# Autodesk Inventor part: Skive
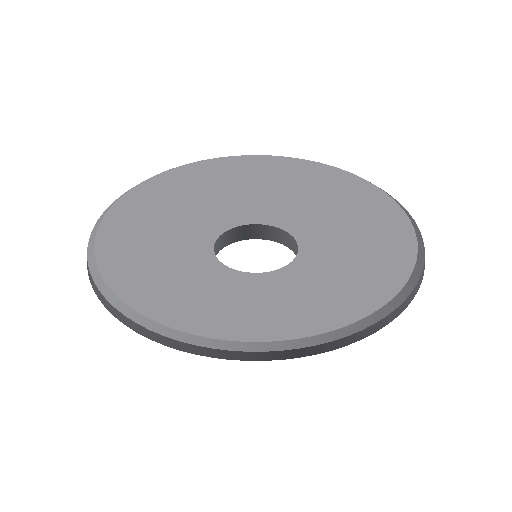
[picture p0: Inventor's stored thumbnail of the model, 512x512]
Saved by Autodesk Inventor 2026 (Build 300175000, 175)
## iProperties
Created: 2013-10
Part Number: Skive
Material: Generic
Document SubType Name: Modeling
Designer: Cadskolen
Density: 1 g/cm^3
Appearance: Default
Author: Cadskolen
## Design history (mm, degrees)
sketch "Sketch1"
  geometry: C1 r 12 at (0, 0); C2 r 3 at (0, 0); 1 further point
  constraints: 2 centre point, 2 coincident
  dimensions: "d0" = 24 diameter of C1; "d1" = 6 diameter of C2
extrude "Extrusion1" new body sketch "Sketch1" distance "d2" = 1.3; taper "d3" = 0 deg
chamfer "Chamfer1" distance "d4" = 0.5; stored, may be unused: second distance "d5" = 2, angle "d6" = 45 deg
body "Solid1"
